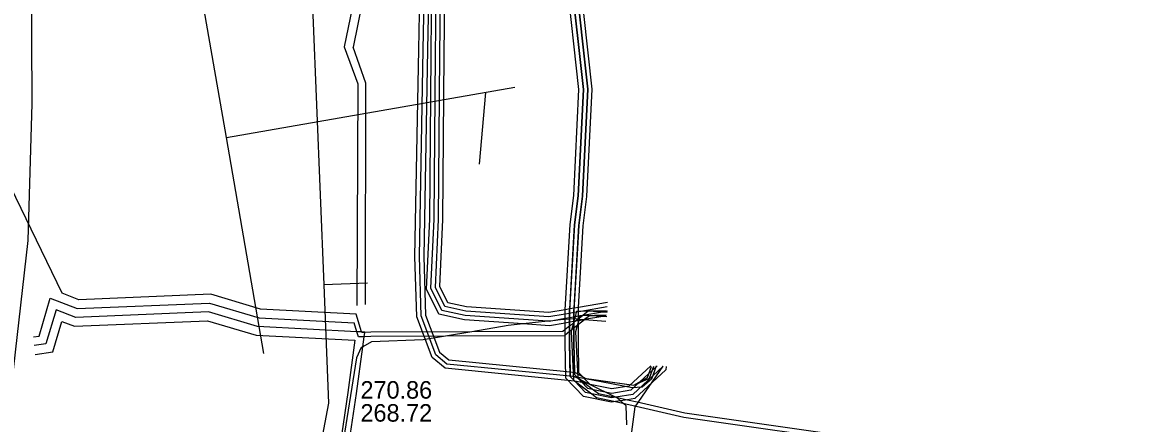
# Model space of a CAD drawing. Extents: x -598233 to -596890, y -1157848 to -1156431.
# Drawn here: x -598008.8 to -597957.3, y -1156845.2 to -1156826.9 of the extents above; entities that cross this region are included whole.
import ezdxf

# ---------------------------------------------------------------- set-up
doc = ezdxf.new("R2010")
doc.units = 0
for name, color, linetype in [('Vrstva 1', 7, 'Continuous'), ('Vrstva 13', 7, 'Continuous'), ('Vrstva 42', 7, 'Continuous'), ('Vrstva 44', 7, 'Continuous'), ('Vrstva 5', 7, 'Continuous'), ('Vrstva 8', 7, 'Continuous')]:
    doc.layers.add(name, color=color, linetype=linetype)

msp = doc.modelspace()

# ---------------------------------------------------------------- linework, layer by layer
at = {"layer": 'Vrstva 1'}
msp.add_line((-597987.97, -1156833.41), (-597987.668, -1156830.135), dxfattribs=at)
for points in [[(-597997.805, -1156842.052), (-597999.52, -1156832.19), (-598001.3, -1156821.99), (-598003.19, -1156811.11), (-598004.51, -1156803.5), (-598004.86, -1156801.52), (-598005.124, -1156800), (-598006.06, -1156794.6), (-598006.18, -1156793.94), (-598006.299, -1156793.258)], [(-597999.52, -1156832.19), (-597986.345, -1156829.896)], [(-597987.97, -1156833.41), (-597987.668, -1156830.135)]]:
    msp.add_lwpolyline(points, dxfattribs=at)
at = {"layer": 'Vrstva 13'}
msp.add_lwpolyline([(-598009.486, -1156844.942), (-598008.563, -1156836.883), (-598008.389, -1156830.63), (-598008.486, -1156809.562), (-598008.55, -1156808.73)], dxfattribs=at)
at = {"layer": 'Vrstva 42'}
for points in [[(-597993.599, -1156840.248), (-597997.958, -1156840.024), (-598000.235, -1156839.346), (-598006.26, -1156839.595), (-598007.024, -1156839.3), (-598014.08, -1156824.73), (-598016.82, -1156821.64), (-598025.15, -1156818.11), (-598055.043, -1156816.021), (-598055.12, -1156815.368)], [(-597993.431, -1156824.585), (-597994.139, -1156828.054)], [(-597982.123, -1156840.119), (-597982.346, -1156840.157), (-597983.249, -1156840.314), (-597983.321, -1156840.327), (-597983.386, -1156840.338), (-597983.45, -1156840.349), (-597983.603, -1156840.375), (-597983.65, -1156840.384), (-597983.85, -1156840.418), (-597984.05, -1156840.453), (-597984.615, -1156840.551), (-597984.785, -1156840.581), (-597984.848, -1156840.576), (-597988.614, -1156840.309), (-597989.688, -1156840.078), (-597990.181, -1156839.071), (-597990.03, -1156835.917), (-597989.97, -1156828.429), (-597989.934, -1156824.581)], [(-597982.133, -1156839.917), (-597983.344, -1156840.127), (-597983.45, -1156840.146), (-597983.545, -1156840.162), (-597983.65, -1156840.181), (-597983.85, -1156840.215), (-597984.05, -1156840.25), (-597984.795, -1156840.379), (-597988.586, -1156840.111), (-597989.552, -1156839.903), (-597989.979, -1156839.029), (-597989.83, -1156835.923), (-597989.77, -1156828.431), (-597989.732, -1156824.406)], [(-597982.118, -1156839.712), (-597983.442, -1156839.941), (-597983.644, -1156839.977), (-597983.846, -1156840.012), (-597984.049, -1156840.047), (-597984.805, -1156840.178), (-597988.558, -1156839.912), (-597989.414, -1156839.727), (-597989.777, -1156838.987), (-597989.63, -1156835.928), (-597989.57, -1156828.433), (-597989.531, -1156824.231)], [(-597980.135, -1156842.605), (-597981.147, -1156843.538), (-597981.924, -1156843.665), (-597982.917, -1156843.465), (-597983.422, -1156842.928), (-597983.45, -1156841.537), (-597983.45, -1156840.729), (-597983.45, -1156840.579), (-597983.45, -1156840.552), (-597983.45, -1156840.486), (-597983.45, -1156840.474), (-597983.45, -1156840.349), (-597983.45, -1156840.146), (-597983.45, -1156840.13), (-597983.45, -1156840.088), (-597983.442, -1156839.941), (-597983.231, -1156836.218), (-597983.061, -1156834.886), (-597982.819, -1156829.981), (-597983.395, -1156824.709)], [(-597993.103, -1156824.978), (-597993.734, -1156828.069)], [(-597982.186, -1156840.332), (-597982.336, -1156840.358), (-597983.165, -1156840.502), (-597983.185, -1156840.506), (-597983.443, -1156840.551), (-597983.45, -1156840.552), (-597983.576, -1156840.574), (-597983.65, -1156840.587), (-597983.66, -1156840.588), (-597983.85, -1156840.621), (-597984.05, -1156840.656), (-597984.775, -1156840.782), (-597985.972, -1156840.697), (-597988.642, -1156840.508), (-597989.825, -1156840.253), (-597990.383, -1156839.113), (-597990.23, -1156835.912), (-597990.17, -1156828.427), (-597990.136, -1156824.756)], [(-597979.437, -1156842.634), (-597979.451, -1156842.788), (-597980.873, -1156844.102), (-597981.207, -1156844.156), (-597981.747, -1156844.244), (-597981.936, -1156844.275), (-597983.223, -1156844.015), (-597984.018, -1156843.172), (-597984.05, -1156841.543), (-597984.05, -1156841.213), (-597984.05, -1156840.954), (-597984.05, -1156840.656), (-597984.05, -1156840.494), (-597984.05, -1156840.453), (-597984.05, -1156840.25), (-597984.05, -1156840.072), (-597984.049, -1156840.047), (-597983.829, -1156836.162), (-597983.659, -1156834.834), (-597983.421, -1156829.999), (-597983.985, -1156824.831)], [(-597979.572, -1156842.629), (-597980.964, -1156843.914), (-597981.74, -1156844.041), (-597981.932, -1156844.072), (-597982.84, -1156843.889), (-597983.121, -1156843.832), (-597983.633, -1156843.289), (-597983.669, -1156843.251), (-597983.819, -1156843.091), (-597983.85, -1156841.541), (-597983.85, -1156841.05), (-597983.85, -1156840.792), (-597983.85, -1156840.621), (-597983.85, -1156840.482), (-597983.85, -1156840.418), (-597983.85, -1156840.215), (-597983.85, -1156840.077), (-597983.846, -1156840.012), (-597983.63, -1156836.181), (-597983.46, -1156834.851), (-597983.22, -1156829.993), (-597983.788, -1156824.79)], [(-597979.852, -1156842.615), (-597981.056, -1156843.726), (-597981.928, -1156843.868), (-597982.756, -1156843.701), (-597983.019, -1156843.648), (-597983.621, -1156843.009), (-597983.65, -1156841.539), (-597983.65, -1156840.889), (-597983.65, -1156840.633), (-597983.65, -1156840.587), (-597983.65, -1156840.552), (-597983.65, -1156840.471), (-597983.65, -1156840.384), (-597983.65, -1156840.181), (-597983.65, -1156840.083), (-597983.644, -1156839.977), (-597983.43, -1156836.199), (-597983.26, -1156834.869), (-597983.02, -1156829.987), (-597983.592, -1156824.75)], [(-597994.139, -1156828.054), (-597993.516, -1156829.732), (-597993.566, -1156839.852)], [(-597993.168, -1156839.809), (-597993.15, -1156829.709), (-597993.734, -1156828.069)], [(-598008.324, -1156841.289), (-598008.069, -1156841.253), (-598007.558, -1156839.522), (-598006.327, -1156839.998), (-598000.285, -1156839.749), (-597998.026, -1156840.421), (-597993.685, -1156840.643)], [(-598003.78, -1156895.63), (-598002.867, -1156893.497), (-598002.413, -1156890.792), (-598001.763, -1156886.546), (-597997.844, -1156868.129), (-597994.303, -1156848.743), (-597993.572, -1156843.878), (-597993.285, -1156841.737), (-597993.225, -1156841.282), (-597993.198, -1156841.081), (-597993.196, -1156841.069), (-597993.345, -1156841.061), (-597993.558, -1156841.051), (-597998.094, -1156840.819), (-598000.335, -1156840.151), (-598006.393, -1156840.402), (-598007.297, -1156840.053), (-598007.758, -1156841.612), (-598008.29, -1156841.689)], [(-597982.134, -1156840.17), (-597982.346, -1156840.157), (-597982.985, -1156840.119), (-597983.002, -1156840.118), (-597983.004, -1156840.119), (-597983.249, -1156840.314), (-597983.263, -1156840.325), (-597983.414, -1156840.445), (-597983.45, -1156840.474), (-597983.464, -1156840.485), (-597983.576, -1156840.574), (-597983.65, -1156840.633), (-597983.678, -1156840.654), (-597983.813, -1156840.762), (-597983.85, -1156840.792), (-597984.05, -1156840.954), (-597984.156, -1156841.04), (-597988.321, -1156841.054), (-597992.932, -1156841.07), (-597993.198, -1156841.081), (-597993.337, -1156841.087), (-597993.345, -1156841.061), (-597993.599, -1156840.248)], [(-597982.182, -1156840.1), (-597982.985, -1156840.119), (-597983.004, -1156840.119), (-597983.344, -1156840.127), (-597983.45, -1156840.13), (-597983.537, -1156840.132), (-597983.545, -1156840.162), (-597983.603, -1156840.375), (-597983.629, -1156840.472), (-597983.65, -1156840.552), (-597983.66, -1156840.588), (-597983.678, -1156840.654), (-597983.766, -1156840.982), (-597983.781, -1156841.039), (-597983.669, -1156843.251), (-597983.668, -1156843.262), (-597983.633, -1156843.289), (-597982.84, -1156843.889), (-597982.623, -1156844.053), (-597981.747, -1156844.244), (-597980.812, -1156844.448), (-597978.628, -1156844.958), (-597969.883, -1156846.199)], [(-598008.255, -1156842.088), (-598007.447, -1156841.971), (-598007.036, -1156840.582), (-598006.46, -1156840.805), (-598000.385, -1156840.554), (-597998.162, -1156841.216), (-597993.65, -1156841.446), (-597993.968, -1156843.822), (-597994.697, -1156848.677), (-597996.678, -1156859.523), (-597998.236, -1156868.051), (-598001.271, -1156882.312)], [(-597982.2, -1156840.58), (-597983.17, -1156840.507), (-597983.185, -1156840.506), (-597983.426, -1156840.488), (-597983.45, -1156840.486), (-597983.464, -1156840.485), (-597983.629, -1156840.472), (-597983.65, -1156840.471), (-597983.66, -1156840.47), (-597983.85, -1156840.482), (-597984.05, -1156840.494), (-597984.14, -1156840.5), (-597984.615, -1156840.551), (-597984.848, -1156840.576), (-597985.972, -1156840.697), (-597986.65, -1156840.77), (-597988.321, -1156841.054), (-597989.522, -1156841.258), (-597990.53, -1156841.43), (-597992.89, -1156841.51), (-597993.285, -1156841.737), (-597993.36, -1156841.78), (-597993.58, -1156842.24), (-597994.24, -1156846.36)], [(-597982.146, -1156840.37), (-597982.336, -1156840.358), (-597982.938, -1156840.322), (-597983.165, -1156840.502), (-597983.17, -1156840.507), (-597983.45, -1156840.729), (-597983.501, -1156840.77), (-597983.65, -1156840.889), (-597983.687, -1156840.918), (-597983.766, -1156840.982), (-597983.85, -1156841.05), (-597984.05, -1156841.213), (-597984.084, -1156841.24), (-597989.522, -1156841.258), (-597992.928, -1156841.27), (-597993.225, -1156841.282), (-597993.483, -1156841.293), (-597993.558, -1156841.051), (-597993.685, -1156840.643)], [(-597982.178, -1156840.3), (-597983.263, -1156840.325), (-597983.321, -1156840.327), (-597983.383, -1156840.328), (-597983.386, -1156840.338), (-597983.414, -1156840.445), (-597983.426, -1156840.488), (-597983.443, -1156840.551), (-597983.45, -1156840.579), (-597983.501, -1156840.77), (-597983.579, -1156841.061), (-597983.472, -1156843.158), (-597982.756, -1156843.701), (-597982.537, -1156843.867), (-597981.74, -1156844.041), (-597981.207, -1156844.156), (-597980.768, -1156844.252), (-597978.592, -1156844.762), (-597969.857, -1156846.001), (-597962.318, -1156846.971), (-597955.74, -1156847.69)]]:
    msp.add_lwpolyline(points, dxfattribs=at)
at = {"layer": 'Vrstva 44'}
for p, q in [((-597980.2, -1156843.18), (-597980.01, -1156842.63)), ((-597983.61, -1156843.11), (-597980.91, -1156843.49)), ((-597983.011, -1156843.41), (-597983.61, -1156843.11)), ((-597980.91, -1156843.49), (-597980.2, -1156843.18))]:
    msp.add_line(p, q, dxfattribs=at)
for points in [[(-597981.23, -1156845.31), (-597981.26, -1156844.43), (-597981.67, -1156844.08), (-597983.011, -1156843.41), (-597983.63, -1156843.309), (-597989.53, -1156842.723), (-597990.128, -1156842.23), (-597990.829, -1156840.369), (-597990.91, -1156837.621), (-597990.73, -1156828.166), (-597990.56, -1156819.109), (-597990.66, -1156809.698), (-597990.628, -1156808.753), (-597990.889, -1156805.169), (-597991.556, -1156802.999)], [(-597979.902, -1156842.631), (-597980.105, -1156843.213), (-597980.54, -1156843.59), (-597980.99, -1156843.62), (-597982.801, -1156843.268), (-597983.61, -1156843.11), (-597983.819, -1156843.089), (-597989.45, -1156842.53), (-597989.96, -1156842.11), (-597990.63, -1156840.33), (-597990.71, -1156837.62), (-597990.53, -1156828.17), (-597990.36, -1156819.11), (-597990.46, -1156809.69), (-597990.428, -1156808.749), (-597990.691, -1156805.131), (-597991.221, -1156803.406), (-597991.364, -1156802.941)], [(-597991.145, -1156803.107), (-597989.926, -1156805.606), (-597989.613, -1156806.853), (-597988.664, -1156810.631), (-597987.679, -1156813.377), (-597986.445, -1156815.443), (-597985.944, -1156817.872), (-597984.655, -1156821.308), (-597983.592, -1156824.75), (-597983.02, -1156829.987), (-597983.26, -1156834.869), (-597983.43, -1156836.199), (-597983.65, -1156840.083), (-597983.65, -1156841.539), (-597983.623, -1156842.908), (-597983.621, -1156843.009)], [(-597991.335, -1156803.173), (-597991.221, -1156803.406), (-597990.114, -1156805.674), (-597989.777, -1156807.017), (-597988.856, -1156810.689), (-597987.861, -1156813.463), (-597986.635, -1156815.517), (-597986.136, -1156817.928), (-597984.845, -1156821.372), (-597983.788, -1156824.79), (-597983.22, -1156829.993), (-597983.46, -1156834.851), (-597983.63, -1156836.181), (-597983.85, -1156840.077), (-597983.85, -1156841.541), (-597983.823, -1156842.888), (-597983.819, -1156843.089), (-597983.819, -1156843.091)], [(-597990.16, -1156819.111), (-597990.33, -1156828.174), (-597990.51, -1156837.619), (-597990.431, -1156840.291), (-597989.792, -1156841.99), (-597989.37, -1156842.337), (-597983.823, -1156842.888), (-597983.623, -1156842.908), (-597983.59, -1156842.911), (-597983.105, -1156843.181), (-597980.91, -1156843.49), (-597980.295, -1156843.147), (-597980.117, -1156842.647)], [(-597979.593, -1156842.627), (-597980.874, -1156844.477), (-597981.223, -1156847.117), (-597981.758, -1156848.346), (-597983.269, -1156848.71), (-597991.584, -1156848.53), (-597992.674, -1156848.909), (-597993.135, -1156850.071), (-597994.153, -1156853.996), (-597995.792, -1156859.833), (-597996.852, -1156865.581), (-597999.023, -1156874.344)]]:
    msp.add_lwpolyline(points, dxfattribs=at)
at = {"layer": 'Vrstva 5'}
for p, q in [((-597993.071, -1156838.839), (-597995.069, -1156838.92)), ((-597994.85, -1156844.31), (-598000.95, -1156876.07))]:
    msp.add_line(p, q, dxfattribs=at)
msp.add_lwpolyline([(-597996.241, -1156810.134), (-597995.069, -1156838.92), (-597994.85, -1156844.31)], dxfattribs=at)

# ---------------------------------------------------------------- texts
at = {"layer": 'Vrstva 8'}
for s, p in [('270.86', (-597993.398, -1156844.108)), ('268.72', (-597993.398, -1156845.158))]:
    msp.add_text(s, height=0.8, dxfattribs=at).set_placement(p)

doc.saveas('drawing.dxf')
